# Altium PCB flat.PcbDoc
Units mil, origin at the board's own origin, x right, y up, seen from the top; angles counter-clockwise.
Board outline 1968.5 x 1181.1 mil, 2 copper layers (Top Layer, Bottom Layer); 4 components, 4 nets, 14 pads, 0 vias.
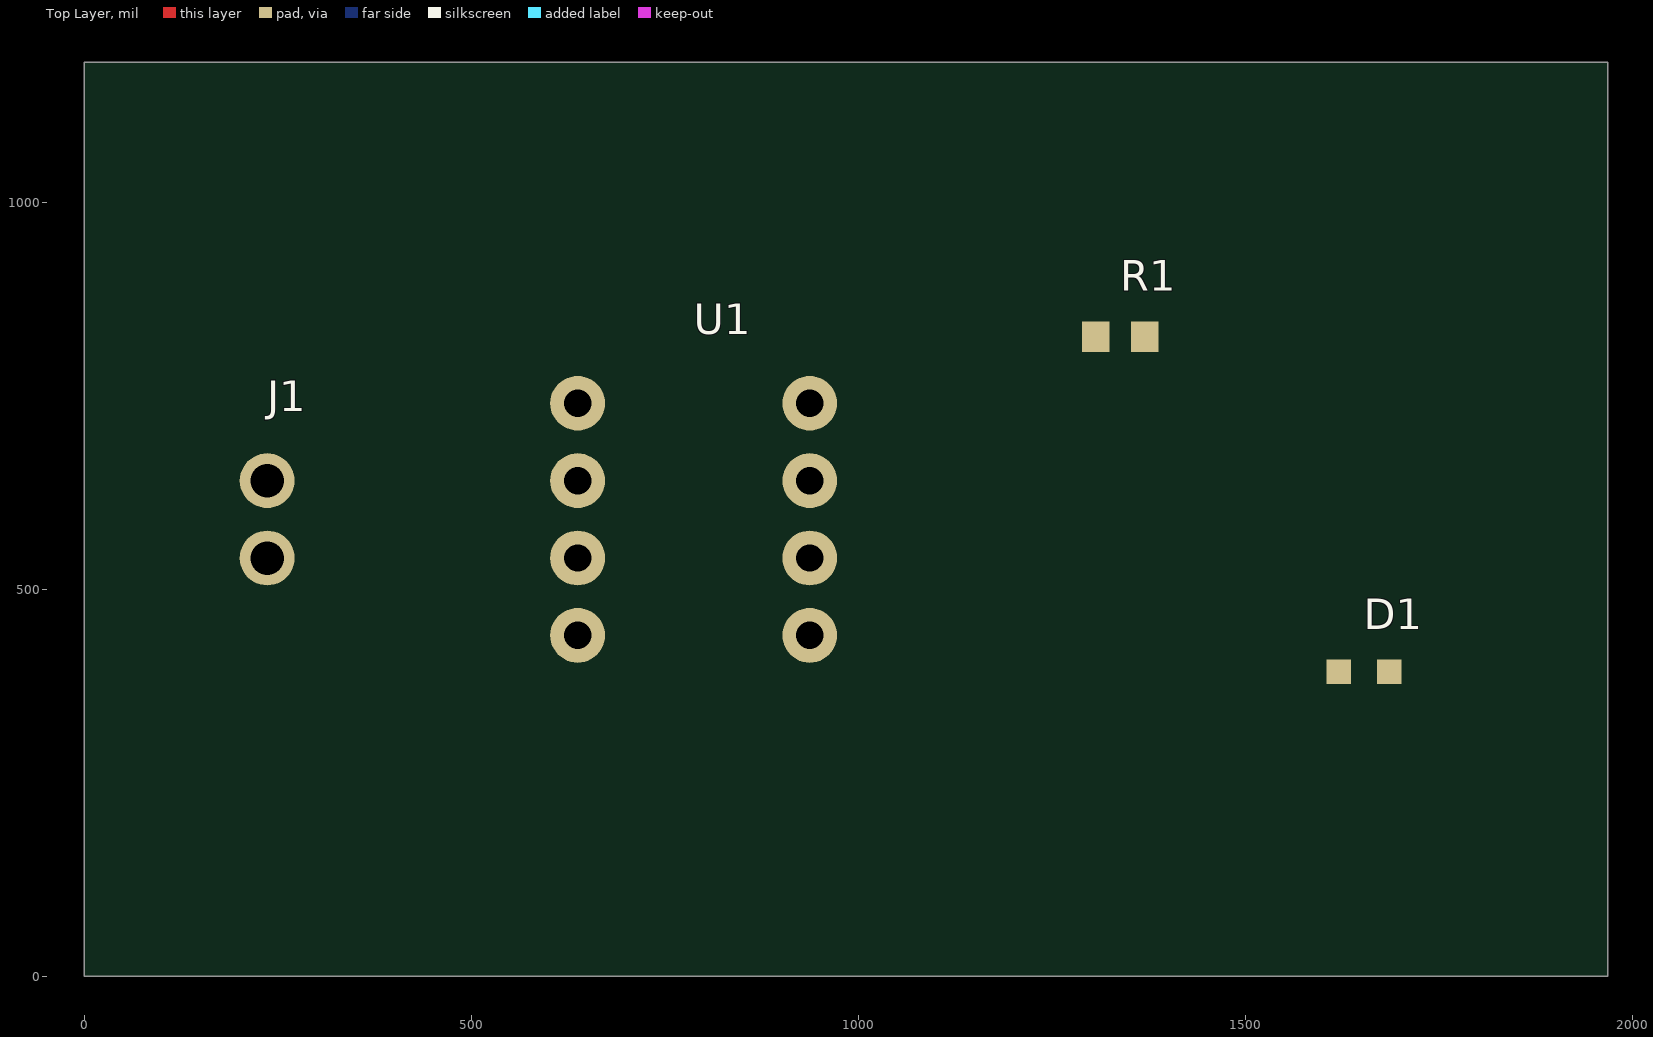
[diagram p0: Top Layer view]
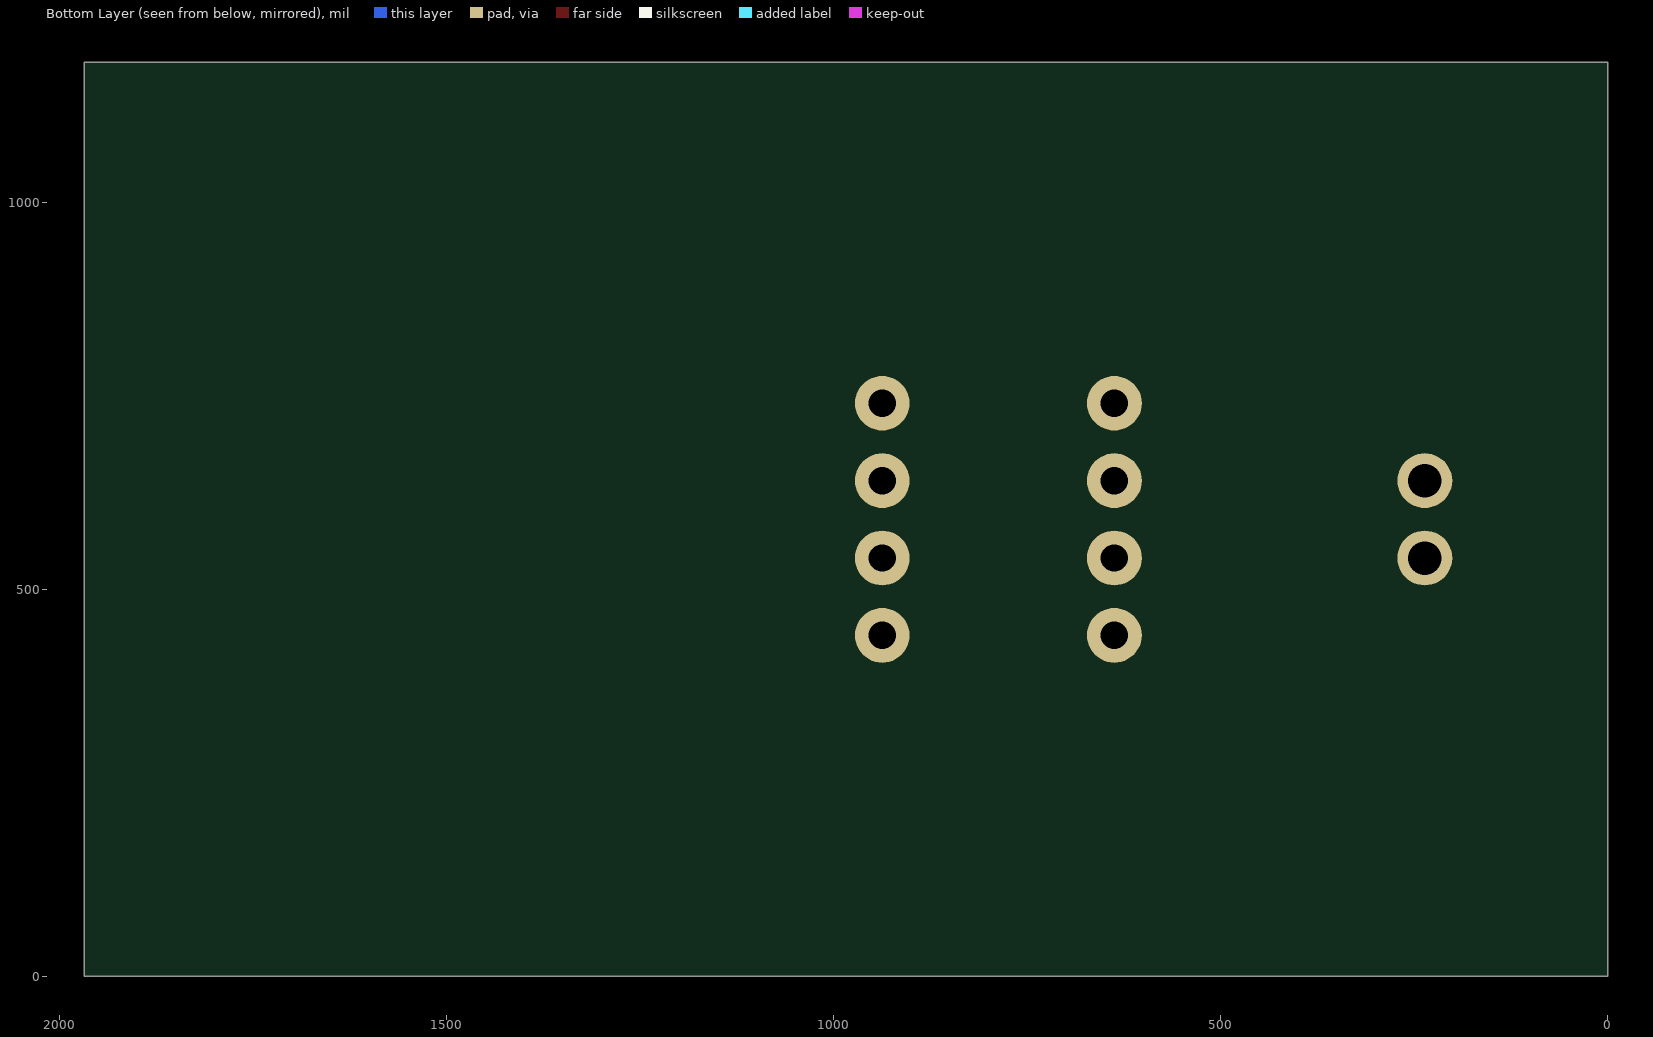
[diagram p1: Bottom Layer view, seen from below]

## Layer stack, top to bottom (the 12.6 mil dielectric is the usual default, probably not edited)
Top Solder: solder mask 0.4, Solder Resist, Dk 3.5
Top Layer: signal copper 1.4
Dielectric 1: dielectric 12.6, FR-4, Dk 4.8
Bottom Layer: signal copper 1.4
Bottom Solder: solder mask 0.4, Solder Resist, Dk 3.5

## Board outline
0,1181.1 1968.5,1181.1 1968.5,0 0,0

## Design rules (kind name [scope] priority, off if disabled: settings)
Clearance Clearance_PWR [InNetClass('PWR')] p1: gap=7.87 ignorepadtopadclearanceinfootprint=FALSE
Clearance [All] p2: gap=7.87 ignorepadtopadclearanceinfootprint=FALSE
RoutingVias [All] p1: holewidth=11.81 width=23.62 viastyle="Through Hole" minholewidth=11.81 minwidth=23.62 maxholewidth=11.81 maxwidth=23.62
Width Width_PWR [InNetClass('PWR')] p1: maxlimit=19.68 minlimit=19.68 preferedwidth=19.68
Width [All] p2: maxlimit=9.84 minlimit=9.84 preferedwidth=9.84

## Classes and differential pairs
net class PWR: GND VIN

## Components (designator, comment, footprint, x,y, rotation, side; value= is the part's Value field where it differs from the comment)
D1 "red" LED0603_Kingbright_APT1608SURCK 1653.54,393.7 r0 top
J1 "SUPPLY" Header_1x2_P2.54 236.22,590.55 r0 top
R1 "330" Chip_0603 1338.58,826.77 r0 top
U1 "MCU" DIP8_Microchip_P 787.4,590.55 r0 top locked

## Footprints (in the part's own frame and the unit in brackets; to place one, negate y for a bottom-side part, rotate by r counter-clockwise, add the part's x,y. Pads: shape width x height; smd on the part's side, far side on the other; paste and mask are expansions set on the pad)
Chip_0603 [mm]
  rect 0.9x1 smd: 1(-0.8,0) 2(0.8,0)
DIP8_Microchip_P [mm]
  round 1.8 hole 0.9: 1(-3.81,-3.81) 2(-3.81,-1.27) 3(-3.81,1.27) 4(-3.81,3.81) 5(3.81,3.81) 6(3.81,1.27) 7(3.81,-1.27) 8(3.81,-3.81)
Header_1x2_P2.54 [mm]
  round 1.8 hole 1.1: 1(0,-1.27) 2(0,1.27)
LED0603_Kingbright_APT1608SURCK [mm]
  rect 0.8x0.8 smd: 1(-0.825,0) 2(0.825,0)

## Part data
D1: library part LED
J1: library part Connector_2
R1: library part Resistor
U1: library part Microcontroller

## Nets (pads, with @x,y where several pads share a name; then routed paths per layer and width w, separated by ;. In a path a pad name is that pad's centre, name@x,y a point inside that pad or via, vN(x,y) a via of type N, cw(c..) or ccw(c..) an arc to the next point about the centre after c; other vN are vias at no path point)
GND: D1.1 J1.2 U1.8
LED_A: D1.2 R1.2
LED_DRV: R1.1 U1.2
VIN: J1.1 U1.1
pads on no net: U1.3 U1.4 U1.5 U1.6 U1.7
